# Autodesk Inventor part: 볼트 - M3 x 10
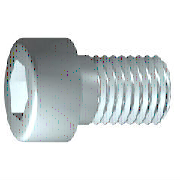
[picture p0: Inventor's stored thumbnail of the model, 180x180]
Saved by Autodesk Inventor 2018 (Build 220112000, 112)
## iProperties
Created: 2012-02
Part Number: 볼트 - M3 x 10
Material: 스테인리스강
Description: 6각 소켓 머리 캡 나사
Document SubType Name: Modeling
Standard: ISO 4762
Designer: mduedu
Standard Revision: Fourth edition 2004-03-01
Standards Organization: ISO
Language: ko-KR
Size Designation: M3 x 10
Categories: <MemberInstance><Categories><Category DisplayName="조임쇠" InternalName="e4da775c-781d-43d5-af7c-5136215cf5a6" Mnemonic="FSTN"><Category DisplayName="볼트" InternalN
Density: 8.08 g/cm^3
Mass: 1.0701 g
Surface Area: 2.01851 cm^2
Volume: 0.132438 cm^3
Appearance: 반광택
IsCustomPart: 0
Author: mduedu
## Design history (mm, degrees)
sketch "스케치1"
  geometry: L1 (-0.867, 0)-(10, 0); L2 (10, 0)-(10, 1.5); L3 (10, 1.5)-(1.25, 1.5); L4 (1.25, 1.5)-(0.943, 1.5); L5 (0.943, 1.5)-(0, 1.5); L6 (0, 1.5)-(0, 2.75); L7 (0, 2.75)-(-3, 2.75); L8 (-3, 2.75)-(-3, 1.443); L9 (-3, 1.443)-(-1.7, 1.443); L10 (-1.7, 1.443)-(-0.867, 0); L11 (-5.6, 0)-(12.6, 0) reference; L12 (0, -0.55)-(0, 3.3) reference; L13 (1.25, 1.5)-(0, 1.5)
  constraints: 22 end point, 6 parallel, 2 collinear, 2 perpendicular, 1 horizontal, 1 point on line
  dimensions: "d1" = 8.75 distance from line of L3.end L2 (= GEL); "d2" = 0.30683 distance of L4.end L3.end (computed from GAL); "d3" = 3 distance between parallel lines of L8 L6 (= KOH); "d4" = 1.3 distance of L8.end L9.end (= INTI); "d5" = 60 deg angle of L10 L1; "d6" = 3 diameter of L3 L1 (= GD); "d7" = 3 diameter of L5 L1 (= BDM); "d8" = 2.88675 diameter of L9 L1 (= 1.1547 x SW); "d9" = 5.5 diameter of L7 L1 (= KOD); "d26" = 10 distance between parallel lines of L12 L2 (= NLG)
revolve "본체" sketch "스케치1" stored, may be unused: angle "d10" = 90 deg
sketch "스케치2"
  geometry: L1 (0, -3.85)-(0, 3.85) reference; L2 (-3.85, 0)-(3.85, 0) reference; L3 (1.443, 0)-(0.722, -1.25); L4 (0.722, -1.25)-(-0.722, -1.25); L5 (-0.722, -1.25)-(-1.443, 0); L6 (-1.443, 0)-(-0.722, 1.25); L7 (-0.722, 1.25)-(0.722, 1.25); L8 (0.722, 1.25)-(1.443, 0); 2 further points
  constraints: 12 end point, 1 coincident, 1 horizontal alignment, 1 point on line, 12 other
extrude "슬롯" join sketch "스케치2" stored distance "d11" = 10; taper "d12" = 0 deg
workplane "Work Plane1"
fillet "Fillet2" dims "d30" = 0.1 (= R)
body "Solid1"
fillet "모깎기1" dims "d17" = 0.3 (= RR)
feature "스레드" dims "d13" = 8.75 (= GEL), "d14" = 0
chamfer "모따기1" distance "d15" = 0.30673 (= -0.5 x SPD + 0.5 x GD); stored, may be unused: second distance "d16" = 0.30673 (= GUL), angle "d27" = 45 deg
other parameters: "GD" = 3 [user parameter; used in 2 equation terms], "NLG" = 10 [user parameter; used in 1 equation term], "GEL" = 8.75 [user parameter; used in 2 equation terms], "KOD" = 5.5 [user parameter; used in 1 equation term], "KOH" = 3 [user parameter; used in 1 equation term], "INTI" = 1.3 [user parameter; used in 1 equation term], "GAL" = 0.30673 (= 0.61345 x PTC) [user parameter; used in 1 equation term], "GUL" = 0.30673 (= 0.61345 x PTC) [user parameter; used in 1 equation term], "BDM" = 3 (= NND) [user parameter; used in 1 equation term], "SW" = 2.5 [user parameter; used in 2 equation terms], "RR" = 0.3 [user parameter; used in 1 equation term], "SPD" = 2.38655 (= NND - 1.2269 x PTC) [user parameter; used in 1 equation term], "d19" = 0, "d28" = 0, "d29" = 0, "R" = 0.1 [user parameter; used in 1 equation term], "TOA" = 30 deg [user parameter], "GD1" = 2.38655 (= THREADDIA - 1.2269 x PTC) [user parameter], "THREADDIA" = 3 [user parameter; used in 1 equation term], "FAWI" = 45 deg [user parameter], "PTC" = 0.5 [user parameter; used in 5 equation terms], "NND" = 3 [user parameter; used in 2 equation terms], "E0" = 2.8875 (= 1.155 x SW) [user parameter]
